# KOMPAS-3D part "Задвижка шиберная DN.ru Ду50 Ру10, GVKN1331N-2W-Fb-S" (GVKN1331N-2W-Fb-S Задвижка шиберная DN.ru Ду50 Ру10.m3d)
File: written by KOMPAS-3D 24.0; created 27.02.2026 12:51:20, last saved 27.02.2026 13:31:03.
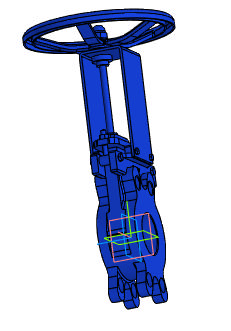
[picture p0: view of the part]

Document properties: Автор: R2D2; Полное имя файла: GVKN1331N-2W-Fb-S Задвижка шиберная DN.ru Ду50 Ру10.cdw

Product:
- Part/product: Задвижка шиберная DN.ru Ду50 Ру10  | designation GVKN1331N-2W-Fb-S
    Масса: 6.5
    Раздел спецификации: Прочие изделия
    Форматы листов документа: A3
    Примечание: D040-07898
    additional columns: D040-07898

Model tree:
1. Операция без истории:1

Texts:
  GVKN1331N-2W-Fb-S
